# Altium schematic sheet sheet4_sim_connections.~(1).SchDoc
size A3; SheetNumber: 2; SheetTotal: 4
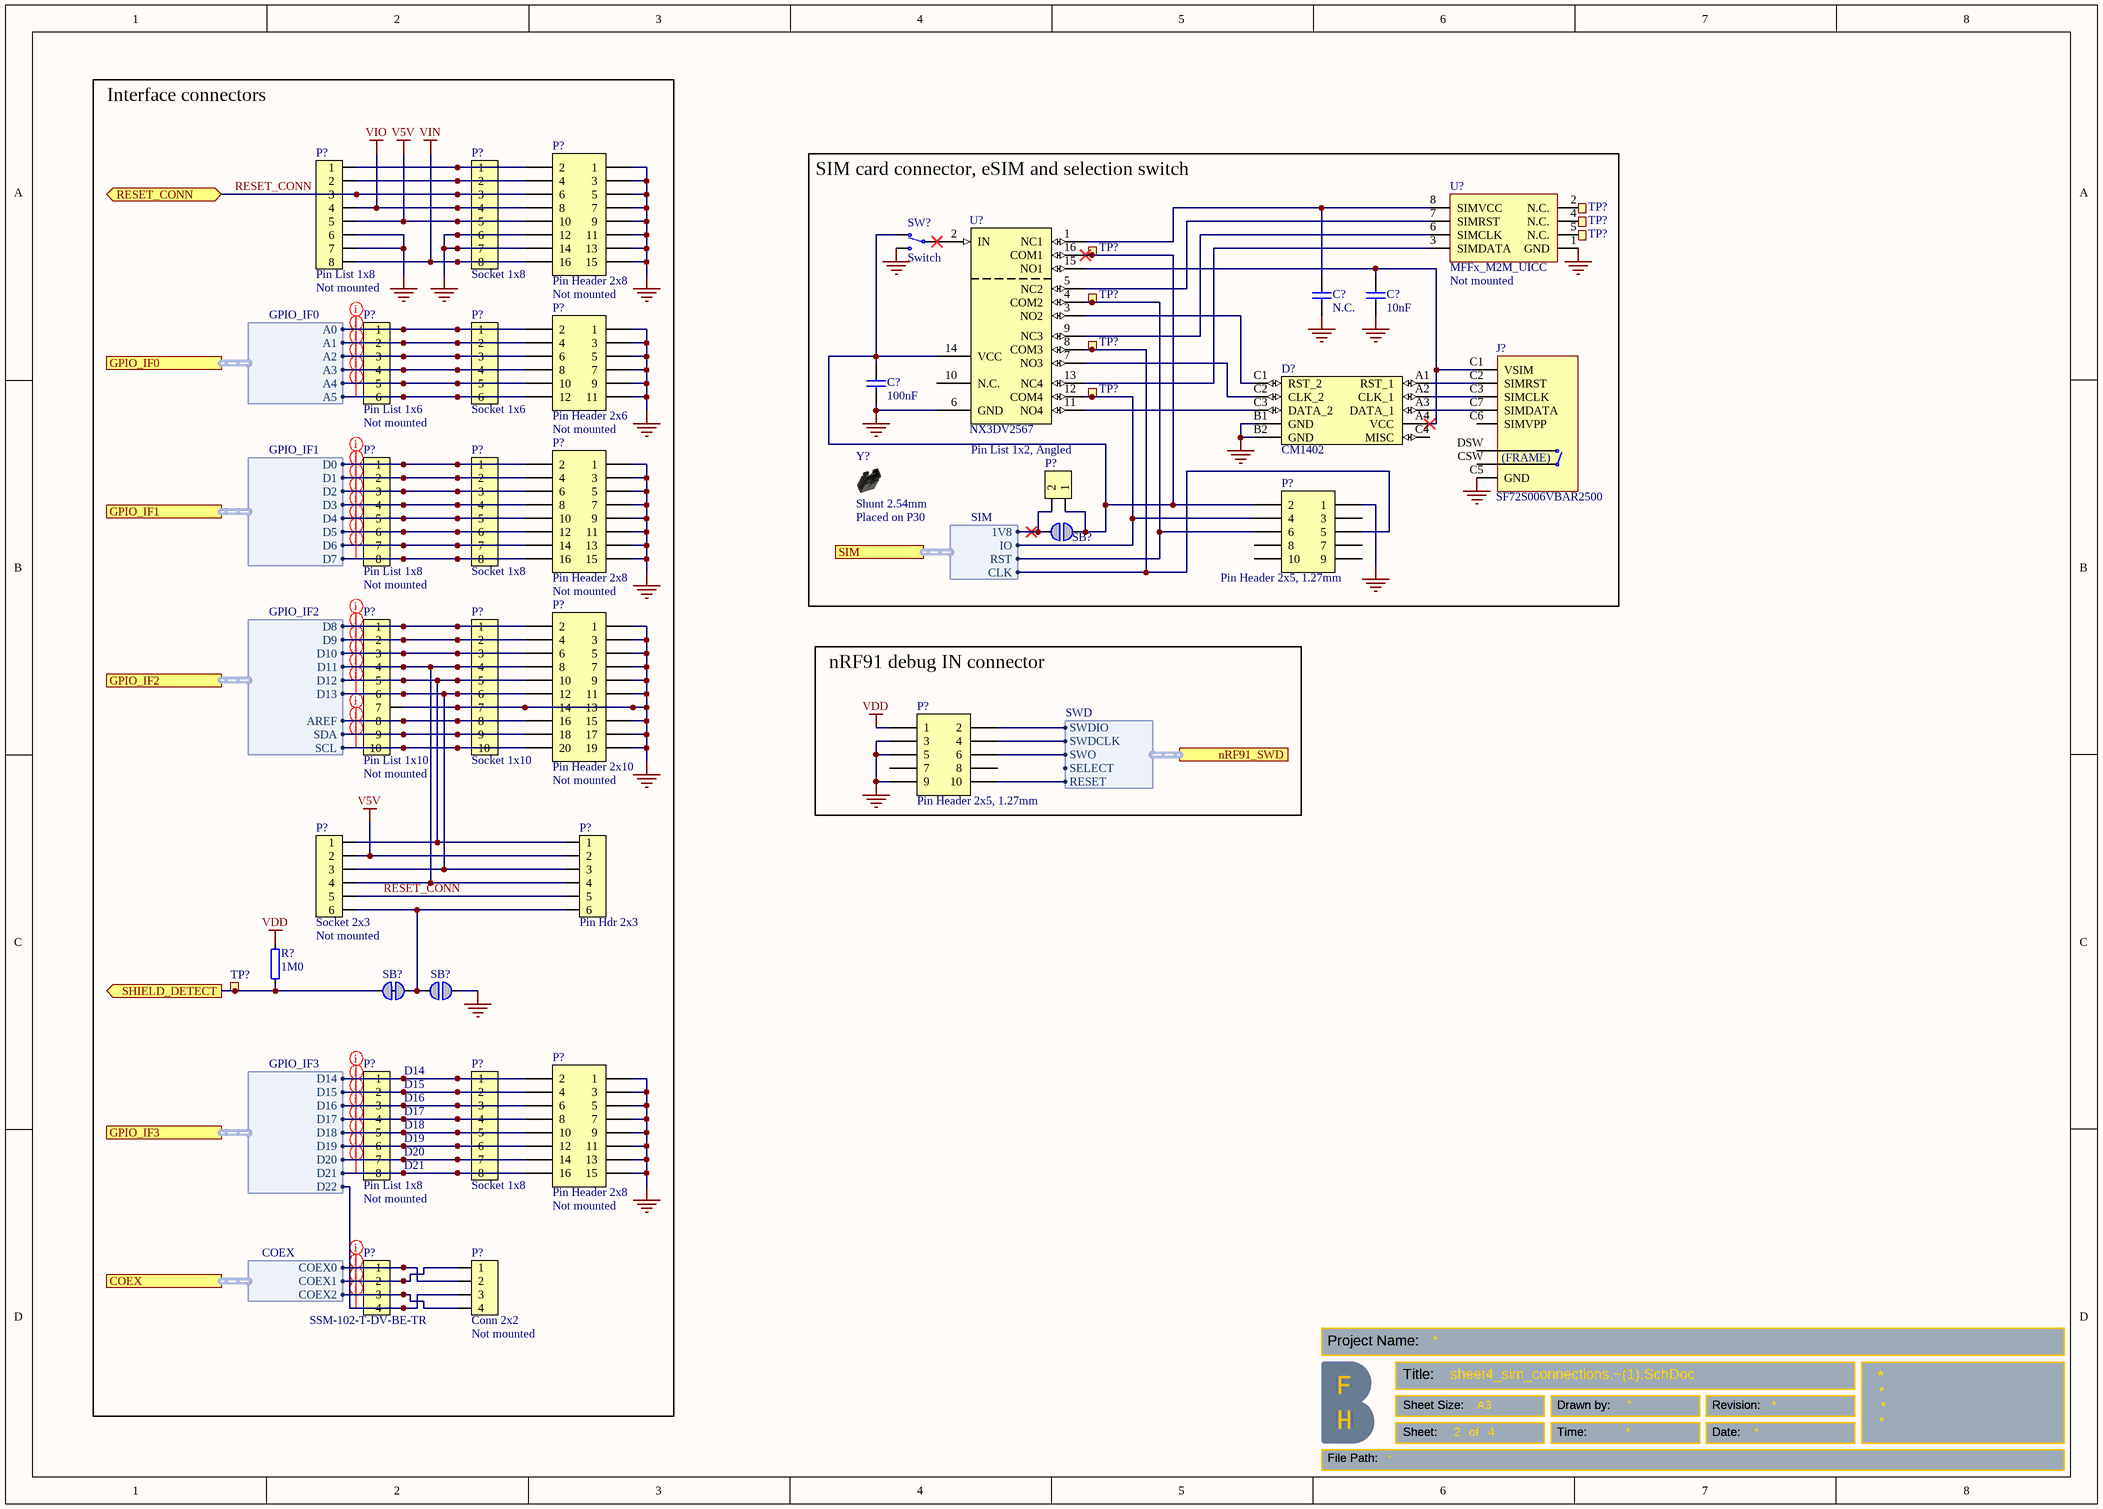
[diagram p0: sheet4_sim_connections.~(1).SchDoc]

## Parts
(Parts that share a designator on the sheet are numbered #1, #2 ... from top to bottom, then left to right.)
C?#1  10nF  [CAPC0603X03L_C]
C?#2  N.C.  [CAPC0603X03L_C_NC]
C?#3  100nF  [CAPC0603X03L_C]
D?  CM1402  [CM1402]
J?  SF72S006VBAR2500  [SF72S006VBAR2500]
P?#1  Pin Header 2x8  Assembly: Not mounted  [HDR_2x8-NC]
P?#2  Pin List 1x8  Assembly: Not mounted  [LIST_1x8_SMD-NC]
P?#3  Socket 1x8  [SOCKET_1x8_SMD]
P?#4  Pin Header 2x6  Assembly: Not mounted  [HDR_2x6-NC]
P?#5  Pin List 1x6  Assembly: Not mounted  [LIST_1x6_SMD-NC]
P?#6  Socket 1x6  [SOCKET_1x6_SMD]
P?#7  Pin Header 2x8  Assembly: Not mounted  [HDR_2x8-NC]
P?#8  Pin List 1x8  Assembly: Not mounted  [LIST_1x8_SMD-NC]
P?#9  Socket 1x8  [SOCKET_1x8_SMD]
P?#10  Pin Header 2x5, 1.27mm  [HDR_2x5-SMD-1.27mm]
P?#11  Pin List 1x2, Angled  [LIST_ANG_1x2-SMD-2.54MM]
P?#12  Pin Header 2x10  Assembly: Not mounted  [HDR_2x10-NC]
P?#13  Pin List 1x10  Assembly: Not mounted  [LIST_1x10_SMD-NC]
P?#14  Socket 1x10  [SOCKET_1x10_SMD]
P?#15  Pin Header 2x5, 1.27mm  [HDR_2x5-SMD-1.27mm-K]
P?#16  Socket 2x3  Assembly: Not mounted  [SOCKET_2x3_SMD-2.54mm-bottom-NC]
P?#17  Pin Hdr 2x3  [HDR_2x3-SMD]
P?#18  Pin Header 2x8  Assembly: Not mounted  [HDR_2x8-NC]
P?#19  Pin List 1x8  Assembly: Not mounted  [LIST_1x8_SMD-NC]
P?#20  Socket 1x8  [SOCKET_1x8_SMD]
P?#21  SSM-102-T-DV-BE-TR  [SSM-102-T-DV-BE-TR]
P?#22  Conn 2x2  Assembly: Not mounted  [HDR_2x2-SMD]
R?  1M0  [RESC0603X03L_C]
SB?#1  Solderbridge  [Solderbridge]  (value not drawn)  (no BOM)
SB?#2  Solderbridge  [Solderbridge_Shorted]  (value not drawn)  (net tie, no BOM)
SB?#3  Solderbridge  [Solderbridge]  (value not drawn)  (no BOM)
SW?  Switch  [CJS-120xA]
TP?#1  Ø1.0mm,SMD  [TP_SMD_D1.0mm]  (value not drawn)  (no BOM)
TP?#2  Ø1.0mm,SMD  [TP_SMD_D1.0mm]  (value not drawn)  (no BOM)
TP?#3  Ø1.0mm,SMD  [TP_SMD_D1.0mm]  (value not drawn)  (no BOM)
TP?#4  Ø1.5mm,SMD  [TP_SMD_D1.5mm]  (value not drawn)  (no BOM)
TP?#5  Ø1.5mm,SMD  [TP_SMD_D1.5mm]  (value not drawn)  (no BOM)
TP?#6  Ø1.5mm,SMD  [TP_SMD_D1.5mm]  (value not drawn)  (no BOM)
TP?#7  Ø1.5mm,SMD  [TP_SMD_D1.5mm]  (value not drawn)  (no BOM)
TP?#8  Ø1.5mm,SMD  [TP_SMD_D1.5mm]  (value not drawn)  (no BOM)
U?#1  MFFx_M2M_UICC  Assembly: Not mounted  [SON127P600X90_HS-8N]
U?#2  NX3DV2567  [XQFN40P180X260X50-16N]
Y?  Shunt 2.54mm  Assembly: Placed on P30  [Shunt_2.54mm_Horizontal]

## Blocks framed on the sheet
Interface connectors: P?#1-P?#9 P?#12-P?#14 P?#16-P?#22 R? SB?#2 SB?#3 TP?#8
SIM card connector, eSIM and selection switch: C?#1-C?#3 D? J? P?#10 P?#11 SB?#1 SW? TP?#1-TP?#7 U?#1 U?#2 Y?
nRF91 debug IN connector: P?#15

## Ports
COEX (harness COEX), GPIO_IF0 (harness GPIO_IF0), GPIO_IF1 (harness GPIO_IF1), GPIO_IF2 (harness GPIO_IF2), GPIO_IF3 (harness GPIO_IF3), nRF91_SWD (harness SWD, see sheet1_connections[3A]), RESET_CONN (bidir), SHIELD_DETECT (out), SIM (harness SIM, see sheet1_connections[3A])

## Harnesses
SWD: SWDIO, SWDCLK, SWO, RESET, SELECT
GPIO_IF0: A0, A1, A2, A3, A4, A5
GPIO_IF1: D0, D1, D2, D3, D4, D5, D6, D7
GPIO_IF2: D8, D9, D10, D11, D12, D13, AREF, SDA, SCL
GPIO_IF3: D14, D15, D16, D17, D18, D19, D20, D21, D22
COEX: COEX0, COEX2, COEX1
SIM: CLK, IO, 1V8, RST

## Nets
GND: C?#1.2 C?#2.1 C?#3.1 D?.B1(GND) D?.B2(GND) J?.0(GND) J?.C5(GND) P?#1.1 P?#1.3 P?#1.5 P?#1.7 P?#1.9 P?#1.11 P?#1.12 P?#1.13 P?#1.14 P?#1.15 P?#2.6 P?#2.7 P?#3.6 P?#3.7 P?#4.1 P?#4.3 P?#4.5 P?#4.7 P?#4.9 P?#4.11 P?#7.1 P?#7.3 P?#7.5 P?#7.7 P?#7.9 P?#7.11 P?#7.13 P?#7.15 P?#10.1 P?#12.1 P?#12.3 P?#12.5 P?#12.7 P?#12.9 P?#12.11 P?#12.13 P?#12.14 P?#12.15 P?#12.17 P?#12.19 P?#13.7 P?#14.7 P?#15.3 P?#15.5 P?#15.9 P?#18.1 P?#18.3 P?#18.5 P?#18.7 P?#18.9 P?#18.11 P?#18.13 P?#18.15 SB?#3.1 SW?.3(N.O) U?#1.1(GND) U?#2.6(GND)
V5V: P?#1.10 P?#2.5 P?#3.5 P?#16.2 P?#17.2
VDD: P?#15.1 R?.2
VIN: P?#1.16 P?#2.8 P?#3.8
VIO: P?#1.8 P?#2.4 P?#3.4
RESET_CONN: P?#1.6 P?#2.3 P?#3.3 P?#16.5 P?#17.5 ; port RESET_CONN
SHIELD_DETECT: R?.1 SB?#2.2 TP?#8.1 ; port SHIELD_DETECT
NetC?#1_1: C?#1.1 D?.A4(VCC) J?.C1(VSIM) U?#2.15(NO1)
NetC?#2_2: C?#2.2 U?#1.8(SIMVCC) U?#2.1(NC1)
NetC?#3_2: C?#3.2 P?#10.2 P?#11.1 SB?#1.2 SW?.1(N.C) TP?#4.1 U?#2.14(VCC) U?#2.16(COM1)
NetD?_A1: D?.A1(RST_1) J?.C2(SIMRST)
NetD?_A2: D?.A2(CLK_1) J?.C3(SIMCLK)
NetD?_A3: D?.A3(DATA_1) J?.C7(SIMDATA)
NetD?_C1: D?.C1(RST_2) U?#2.3(NO2)
NetD?_C2: D?.C2(CLK_2) U?#2.7(NO3)
NetD?_C3: D?.C3(DATA_2) U?#2.11(NO4)
NetP?#1_2: P?#1.2 P?#2.1 P?#3.1
NetP?#1_4: P?#1.4 P?#2.2 P?#3.2
NetP?#4_2: P?#4.2 P?#5.1 P?#6.1 ; port GPIO_IF0.A0
NetP?#4_4: P?#4.4 P?#5.2 P?#6.2 ; port GPIO_IF0.A1
NetP?#4_6: P?#4.6 P?#5.3 P?#6.3 ; port GPIO_IF0.A2
NetP?#4_8: P?#4.8 P?#5.4 P?#6.4 ; port GPIO_IF0.A3
NetP?#4_10: P?#4.10 P?#5.5 P?#6.5 ; port GPIO_IF0.A4
NetP?#4_12: P?#4.12 P?#5.6 P?#6.6 ; port GPIO_IF0.A5
NetP?#7_2: P?#7.2 P?#8.1 P?#9.1 ; port GPIO_IF1.D0
NetP?#7_4: P?#7.4 P?#8.2 P?#9.2 ; port GPIO_IF1.D1
NetP?#7_6: P?#7.6 P?#8.3 P?#9.3 ; port GPIO_IF1.D2
NetP?#7_8: P?#7.8 P?#8.4 P?#9.4 ; port GPIO_IF1.D3
NetP?#7_10: P?#7.10 P?#8.5 P?#9.5 ; port GPIO_IF1.D4
NetP?#7_12: P?#7.12 P?#8.6 P?#9.6 ; port GPIO_IF1.D5
NetP?#7_14: P?#7.14 P?#8.7 P?#9.7 ; port GPIO_IF1.D6
NetP?#7_16: P?#7.16 P?#8.8 P?#9.8 ; port GPIO_IF1.D7
NetP?#10_4: P?#10.4 TP?#7.1 U?#2.12(COM4) ; port SIM.IO
NetP?#10_5: P?#10.5 TP?#6.1 U?#2.8(COM3) ; port SIM.CLK
NetP?#10_6: P?#10.6 TP?#5.1 U?#2.4(COM2) ; port SIM.RST
NetP?#11_2: P?#11.2 SB?#1.1 ; port SIM.1V8
NetP?#12_2: P?#12.2 P?#13.1 P?#14.1 ; port GPIO_IF2.D8
NetP?#12_4: P?#12.4 P?#13.2 P?#14.2 ; port GPIO_IF2.D9
NetP?#12_6: P?#12.6 P?#13.3 P?#14.3 ; port GPIO_IF2.D10
NetP?#12_8: P?#12.8 P?#13.4 P?#14.4 P?#16.4 P?#17.4 ; port GPIO_IF2.D11
NetP?#12_10: P?#12.10 P?#13.5 P?#14.5 P?#16.1 P?#17.1 ; port GPIO_IF2.D12
NetP?#12_12: P?#12.12 P?#13.6 P?#14.6 P?#16.3 P?#17.3 ; port GPIO_IF2.D13
NetP?#12_16: P?#12.16 P?#13.8 P?#14.8 ; port GPIO_IF2.AREF
NetP?#12_18: P?#12.18 P?#13.9 P?#14.9 ; port GPIO_IF2.SDA
NetP?#12_20: P?#12.20 P?#13.10 P?#14.10 ; port GPIO_IF2.SCL
NetP?#15_2: P?#15.2 ; port nRF91_SWD.SWDIO
NetP?#15_4: P?#15.4 ; port nRF91_SWD.SWDCLK
NetP?#15_6: P?#15.6 ; port nRF91_SWD.SWO
NetP?#15_10: P?#15.10 ; port nRF91_SWD.RESET
NetP?#16_6: P?#16.6 P?#17.6 SB?#2.1 SB?#3.2
NetP?#18_2: P?#18.2 P?#19.1 P?#20.1 ; port GPIO_IF3.D14
NetP?#18_4: P?#18.4 P?#19.2 P?#20.2 ; port GPIO_IF3.D15
NetP?#18_6: P?#18.6 P?#19.3 P?#20.3 ; port GPIO_IF3.D16
NetP?#18_8: P?#18.8 P?#19.4 P?#20.4 ; port GPIO_IF3.D17
NetP?#18_10: P?#18.10 P?#19.5 P?#20.5 ; port GPIO_IF3.D18
NetP?#18_12: P?#18.12 P?#19.6 P?#20.6 ; port GPIO_IF3.D19
NetP?#18_14: P?#18.14 P?#19.7 P?#20.7 ; port GPIO_IF3.D20
NetP?#18_16: P?#18.16 P?#19.8 P?#20.8 ; port GPIO_IF3.D21
NetP?#21_1: P?#21.1 P?#22.2 ; port COEX.COEX0
NetP?#21_2: P?#21.2 P?#22.1 ; port COEX.COEX1
NetP?#21_3: P?#21.3 P?#22.4 ; port COEX.COEX2
NetP?#21_4: P?#21.4 P?#22.3 ; port GPIO_IF3.D22
NetSW?_2: SW?.2(COM) U?#2.2(IN)
NetTP?#1_1: TP?#1.1 U?#1.2(N.C.)
NetTP?#2_1: TP?#2.1 U?#1.4(N.C.)
NetTP?#3_1: TP?#3.1 U?#1.5(N.C.)
NetU?#1_3: U?#1.3(SIMDATA) U?#2.13(NC4)
NetU?#1_6: U?#1.6(SIMCLK) U?#2.9(NC3)
NetU?#1_7: U?#1.7(SIMRST) U?#2.5(NC2)

Not connected (* = marked no-connect by the designer): D? C4(MISC); J? C6(SIMVPP) CSW DSW; P?#10 3 7 8 9 10; P?#15 7 8; U?#2 10(N.C.)

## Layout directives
net class GPIO: NetP?#4_2, NetP?#4_4, NetP?#4_6, NetP?#4_8, NetP?#4_10, NetP?#4_12, NetP?#7_2, NetP?#7_4, NetP?#7_6, NetP?#7_8, NetP?#7_10, NetP?#7_12, NetP?#7_14, NetP?#7_16, NetP?#12_2, NetP?#12_4, NetP?#12_6, NetP?#12_8, NetP?#12_10, NetP?#12_12, NetP?#12_16, NetP?#12_18, NetP?#12_20, NetP?#18_2, NetP?#18_4, NetP?#18_6, NetP?#18_8, NetP?#18_10, NetP?#18_12, NetP?#18_14, NetP?#18_16, NetP?#21_1, NetP?#21_2, NetP?#21_3, NetP?#21_4

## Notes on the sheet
- (near P?#19) D14
- (near P?#19) D15
- (near P?#19) D16
- (near P?#19) D17
- (near P?#19) D18
- (near P?#19) D19
- (near P?#19) D20
- (near P?#19) D21

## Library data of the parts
C?#1 = C0201-10n: Capacitor, X7R, ±10%; Manufacturer: N.A.; Part number IPS: 00000003480; Note: 10V; Pad Count: 2
C?#2 = C0201-N.C.: Not mounted; Manufacturer: N.A.; Note: Chip Cap; Assembly: Not mounted; Pad Count: 2
C?#3 = C0201-100n: Capacitor, X5R, ±10%; Manufacturer: N.A.; Part number IPS: 00000001248, 00000002505; Note: 16V; Pad Count: 2
D? = CM1402: EMI Network Filter Arrays SIM CARD EMI FILTER WITH ESD PROTECTION; Manufacturer: ON Semiconductor; Manufacturer Part Number: CM1402-03CP; Part number IPS: 00000009949; Note: N.A.; Pad Count: 10
J? = SF72S006VBAR2500: n 8 (6 + 2) Position Card Connector NANO SIM Surface Mount, Right Angle Gold; Manufacturer: JAE Electronics; Part number IPS: 00000009956; Note: N.A.; Pad Count: 8
P?#1 P?#7 P?#18 = Pin Header 2x8, N.C.: Pin Header 2x8, 2.54mm (100mil); Manufacturer: N.A.; Pad Count: 16
P?#2 P?#8 P?#19 = Pin List 1x8 SMD, N.C.: Pin List 1x8, 2.54mm (100mil), SMD; Manufacturer: W-CON; Manufacturer Part Number: 1125-1108S0M116R2; Note: N.A.; Artikkelnr Noca: 55010006; Pad Count: 8
P?#3 P?#9 P?#20 = Socket 1x8 SMD: Socket 1x8, 2.54mm (100mil), SMD; Manufacturer: W-CON; Manufacturer Part Number: 2171-108MS0CUNR1; Part number IPS: 00000009963; Note: N.A.; Artikkelnr Noca: 55030002; Pad Count: 8
P?#4 = Pin Header 2x6, N.C.: Pin Header 2x6, 2.54mm (100mil); Manufacturer: N.A.; Pad Count: 12
P?#5 = Pin List 1x6 SMD, N.C.: Pin List 1x6, 2.54mm (100mil), SMD; Manufacturer: W-CON; Manufacturer Part Number: 1125-1106S0M116R2; Note: N.A.; Artikkelnr Noca: 55010026; Pad Count: 6
P?#6 = Socket 1x6 SMD: Socket 1x6, 2.54mm (100mil), SMD; Manufacturer: W-CON; Manufacturer Part Number: 2171-106MS0CUNR1; Part number IPS: 00000009964; Note: N.A.; Artikkelnr Noca: 55030001; Pad Count: 6
P?#10 = Pin Header 2x5 SMD, 1.27mm: Pin Header 2x5, 1.27mm (50mil), SMD; Manufacturer: W-CON; Manufacturer Part Number: 1325-1205S0M078R1; Part number IPS: 00000009970; Note: N.A.; Artikkelnr Noca: 55019196; Pad Count: 10
P?#11 = Pin List Ang 1x2 SMD, 2.54mm: Pin List 1x2, 2.54mm (100mil), Right Angled, SMD; Manufacturer: W-CON; Manufacturer Part Number: 1125B-1102S0Z135R2; Part number IPS: 00000009972; Note: N.A.; Artikkelnr Noca: 55010023; Pad Count: 2
P?#12 = Pin Header 2x10, N.C.: Pin Header 2x10, 2.54mm (100mil); Manufacturer: N.A.; Pad Count: 20
P?#13 = Pin List 1x10 SMD, N.C.: Pin List 1x10, 2.54mm (100mil), SMD; Manufacturer: W-CON; Manufacturer Part Number: 1125-1110S0M116R2; Note: N.A.; Artikkelnr Noca: 55010028; Pad Count: 10
P?#14 = Socket 1x10 SMD: Socket 1x10, 2.54mm (100mil), SMD; Manufacturer: W-CON; Manufacturer Part Number: 2171-110MS0CUNR1; Part number IPS: 00000009965; Note: N.A.; Artikkelnr Noca: 55030004; Pad Count: 10
P?#15 = Pin Header 2x5 SMD, 1.27mm, KS: Pin Header 2x5, 1.27mm (50mil), SMD, Keying Shroud; Manufacturer: W-CON; Manufacturer Part Number: 3132-10MS0BK00R1; Part number IPS: 00000009968; Note: N.A.; Artikkelnr Noca: 55010009; Pad Count: 10
P?#16 = Socket 2x3 SMD Bottom, N.C.: Socket 2x3, 2.54mm (100mil), SMD; Manufacturer: W-CON; Manufacturer Part Number: 2171-203MS0CUNR1; Note: N.A.; Artikkelnr Noca: 55030010; Pad Count: 6
P?#17 = Pin Header 2x3 SMD: Pin Header 2x3, 2.54mm (100mil) SMD; Manufacturer: W-CON; Manufacturer Part Number: 1125-1203S0M116R1; Part number IPS: 00000009966; Part number Norautron: N.A.; Artikkelnr Noca: 55010007; Pad Count: 6
P?#21 = 2171-202MSNCUNR1: .025 SOCKET STRIPS; Manufacturer: W-CON; Part number IPS: 00000001417; Note: N.A.; Pad Count: 4
P?#22 = HDR_2x2_SMD_GOLD: CONN HEADER 4POS .100" VERT 15AU; Manufacturer: Molex; Note: SMD, gold plating; Artikkelnr Noca: N.A.; Pad Count: 4
R? = R0201-1M0: Resistor, ±1%, 0.05W; Manufacturer: N.A.; Part number IPS: 00000001418; Note: Chip Res 1%; Pad Count: 2
SB?#1 SB?#3 = Solderbridge: Manufacturer: N.A.; Pad Count: 2
SB?#2 = Solderbridge Shorted: Shorted Solderbridge; Manufacturer: N.A.; Pad Count: 2
SW? = CJS-1200TA: SMD slide Switch (ON-ON); Manufacturer: Copal Electronics Inc; Part number IPS: 00000009982; Note: N.A.; Artikkelnr Noca: 50019068; Pad Count: 3
TP?#1-TP?#3 = TP_SMD_Ø1.0MM: 1.0mm circular SMD testpad; Manufacturer: Nordic Semiconductor; Manufacturer Part Number: N.A.; Pad Count: 1
TP?#4-TP?#8 = TP_SMD_Ø1.5MM: 1.5mm circular SMD testpad; Manufacturer: Nordic Semiconductor; Manufacturer Part Number: N.A.; Pad Count: 1
U?#1 = M2M_UICC: M2M UICC SIM Card; Manufacturer: N.A.; Pad Count: 8
U?#2 = NX3DV2567GU: Low-ohmic four-pole double-throw analog switch; Manufacturer: NXP Semiconductors; Part number IPS: 00000007816; Note: N.A.; Artikkelnr Noca: 15079317; Pad Count: 16
Y? = SHUNT JUMPER 2.54mm BLACK GOLD Horizontal (obsolete): Shunt Jumper 2.54mm Black; Manufacturer: N.A.; Part number IPS: 00000001916; Note: SHUNT JUMPER .1" BLACK GOLD, h=6.00mm, w=5.00mm; Artikkelnr Noca: 56099001; Pad Count: 2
